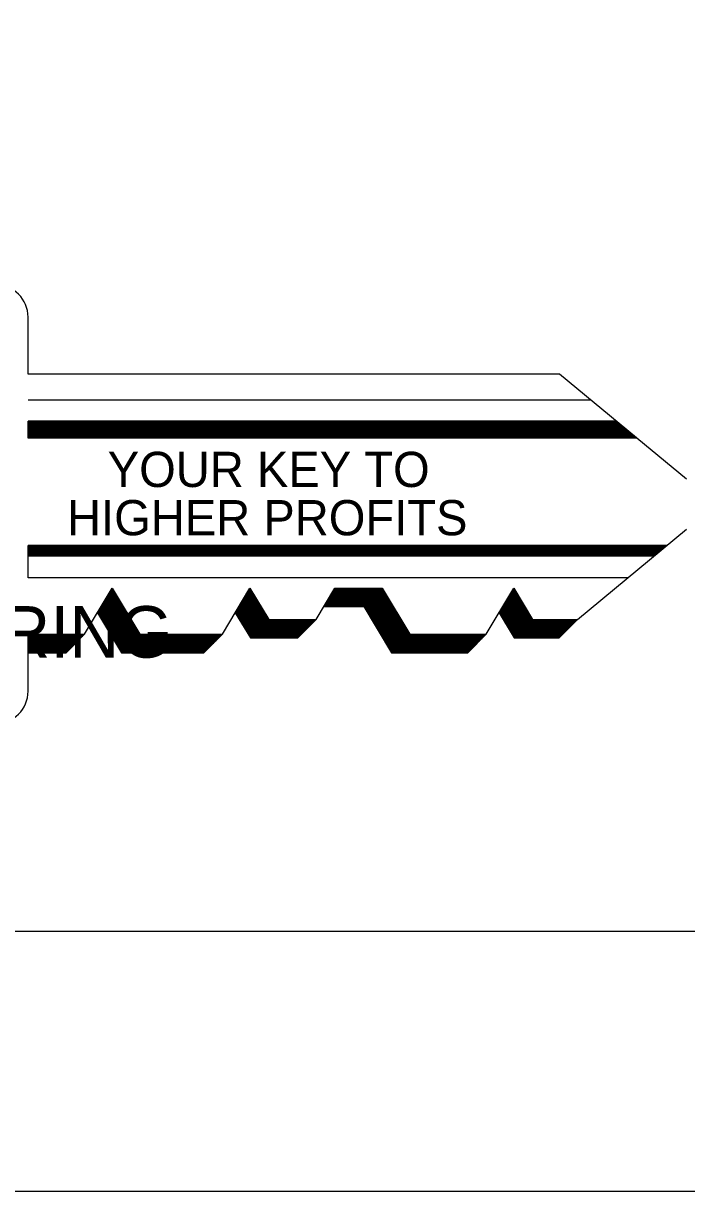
# Model space of a CAD drawing. Extents: x 0 to 53.3, y -2.9 to 37.3.
# Drawn here: x 3.736 to 5.435, y 0.002 to 2.995 of the extents above; entities that cross this region are included whole.
import ezdxf

# ---------------------------------------------------------------- set-up
doc = ezdxf.new("R2010")
doc.units = 0
doc.layers.add('Level 1', color=7, linetype='Continuous')

msp = doc.modelspace()

# ---------------------------------------------------------------- linework, layer by layer
at = {"layer": 'Level 1'}
for p, q in [((3.7484, 2.0961), (3.7484, 2.2419)), ((5.1098, 2.0961), (3.7484, 2.0961)), ((5.3073, 1.9328), (5.1101, 2.0961)), ((5.1904, 2.0294), (3.7484, 2.0294)), ((3.7484, 1.9323), (3.7484, 1.9758)), ((5.2553, 1.9758), (3.7484, 1.9758)), ((5.2566, 1.9748), (3.7484, 1.9748)), ((5.2578, 1.9738), (3.7484, 1.9738)), ((5.2591, 1.9726), (3.7484, 1.9726)), ((5.2606, 1.9714), (3.7484, 1.9714)), ((5.2619, 1.9703), (3.7484, 1.9703)), ((5.2636, 1.9689), (3.7484, 1.9689)), ((5.2649, 1.9678), (3.7484, 1.9678)), ((5.2666, 1.9664), (3.7484, 1.9664)), ((5.2683, 1.9651), (3.7484, 1.9651)), ((5.2696, 1.9639), (3.7484, 1.9639)), ((5.2711, 1.9626), (3.7484, 1.9626)), ((5.2729, 1.9613), (3.7484, 1.9613)), ((5.2743, 1.9601), (3.7484, 1.9601)), ((5.2756, 1.9589), (3.7484, 1.9589)), ((5.2773, 1.9576), (3.7484, 1.9576)), ((5.2789, 1.9563), (3.7484, 1.9563)), ((5.2804, 1.9549), (3.7484, 1.9549)), ((5.2823, 1.9534), (3.7484, 1.9534)), ((5.2838, 1.9523), (3.7484, 1.9523)), ((5.2853, 1.9509), (3.7484, 1.9509)), ((5.2871, 1.9494), (3.7484, 1.9494)), ((5.2888, 1.9481), (3.7484, 1.9481)), ((5.2899, 1.9471), (3.7484, 1.9471)), ((5.2916, 1.9458), (3.7484, 1.9458)), ((5.2708, 1.9629), (5.2703, 1.9634)), ((5.2716, 1.9623), (5.2708, 1.9629)), ((5.2768, 1.9579), (5.2716, 1.9623)), ((5.2791, 1.9561), (5.2768, 1.9579)), ((5.2931, 1.9444), (3.7484, 1.9444)), ((5.2946, 1.9433), (3.7484, 1.9433)), ((5.2959, 1.9421), (3.7484, 1.9421)), ((5.2973, 1.9411), (3.7484, 1.9411)), ((5.2991, 1.9396), (3.7484, 1.9396)), ((5.3003, 1.9386), (3.7484, 1.9386)), ((5.3016, 1.9374), (3.7484, 1.9374)), ((5.3028, 1.9364), (3.7484, 1.9364)), ((5.3041, 1.9354), (3.7484, 1.9354)), ((5.3051, 1.9346), (3.7484, 1.9346)), ((5.3063, 1.9336), (3.7484, 1.9336)), ((5.3071, 1.9329), (3.7484, 1.9329)), ((5.3079, 1.9323), (3.7484, 1.9323)), ((5.3079, 1.9323), (5.3073, 1.9328)), ((5.4354, 1.8269), (5.3079, 1.9323)), ((5.1558, 1.4674), (5.4354, 1.6986)), ((5.3851, 1.6569), (3.7484, 1.6569)), ((3.7484, 1.5743), (3.7484, 1.6569)), ((5.3824, 1.6548), (3.7484, 1.6548)), ((5.3796, 1.6524), (3.7484, 1.6524)), ((5.3764, 1.6498), (3.7484, 1.6498)), ((5.3738, 1.6476), (3.7484, 1.6476)), ((5.3706, 1.6449), (3.7484, 1.6449)), ((5.3678, 1.6426), (3.7484, 1.6426)), ((5.3648, 1.6401), (3.7484, 1.6401)), ((5.3614, 1.6374), (3.7484, 1.6374)), ((5.3584, 1.6349), (3.7484, 1.6349)), ((5.3556, 1.6326), (3.7484, 1.6326)), ((5.3536, 1.6309), (3.7484, 1.6309)), ((5.3518, 1.6294), (3.7484, 1.6294)), ((5.2851, 1.5743), (3.7484, 1.5743)), ((3.8929, 1.4294), (3.9638, 1.5476)), ((3.9518, 1.5273), (3.9759, 1.5273)), ((3.9526, 1.5286), (3.9751, 1.5286)), ((3.9531, 1.5299), (3.9743, 1.5299)), ((3.9539, 1.5313), (3.9736, 1.5313)), ((3.9548, 1.5326), (3.9728, 1.5326)), ((3.9556, 1.5339), (3.9719, 1.5339)), ((3.9564, 1.5353), (3.9711, 1.5353)), ((3.9571, 1.5366), (3.9703, 1.5366)), ((3.9579, 1.5379), (3.9696, 1.5379)), ((3.9588, 1.5393), (3.9688, 1.5393)), ((3.9596, 1.5406), (3.9679, 1.5406)), ((3.9604, 1.5419), (3.9671, 1.5419)), ((3.9611, 1.5433), (3.9664, 1.5433)), ((3.9619, 1.5446), (3.9656, 1.5446)), ((3.9628, 1.5459), (3.9648, 1.5459)), ((3.9638, 1.5476), (4.0344, 1.4294)), ((4.2461, 1.4294), (4.3168, 1.5476)), ((4.3048, 1.5273), (4.3289, 1.5273)), ((4.3056, 1.5286), (4.3281, 1.5286)), ((4.3061, 1.5299), (4.3273, 1.5299)), ((4.3069, 1.5313), (4.3266, 1.5313)), ((4.3078, 1.5326), (4.3258, 1.5326)), ((4.3086, 1.5339), (4.3249, 1.5339)), ((4.3094, 1.5353), (4.3241, 1.5353)), ((4.3101, 1.5366), (4.3233, 1.5366)), ((4.3109, 1.5379), (4.3226, 1.5379)), ((4.3118, 1.5393), (4.3218, 1.5393)), ((4.3126, 1.5406), (4.3209, 1.5406)), ((4.3134, 1.5419), (4.3201, 1.5419)), ((4.3141, 1.5433), (4.3194, 1.5433)), ((4.3148, 1.5443), (4.3188, 1.5443)), ((4.3154, 1.5453), (4.3181, 1.5453)), ((4.3159, 1.5463), (4.3176, 1.5463)), ((4.3168, 1.5476), (4.3649, 1.4674)), ((4.4863, 1.4674), (4.5343, 1.5476)), ((4.5221, 1.5273), (4.6678, 1.5273)), ((4.5229, 1.5286), (4.6669, 1.5286)), ((4.5238, 1.5299), (4.6661, 1.5299)), ((4.5244, 1.5313), (4.6654, 1.5313)), ((4.5253, 1.5326), (4.6646, 1.5326)), ((4.5261, 1.5339), (4.6638, 1.5339)), ((4.5269, 1.5353), (4.6629, 1.5353)), ((4.5276, 1.5366), (4.6621, 1.5366)), ((4.5284, 1.5379), (4.6614, 1.5379)), ((4.5293, 1.5393), (4.6606, 1.5393)), ((4.5301, 1.5406), (4.6598, 1.5406)), ((4.5309, 1.5419), (4.6589, 1.5419)), ((4.5316, 1.5431), (4.6583, 1.5431)), ((4.5323, 1.5443), (4.6576, 1.5443)), ((4.5329, 1.5454), (4.6569, 1.5454)), ((4.5336, 1.5464), (4.6563, 1.5464)), ((4.5343, 1.5476), (4.6556, 1.5476)), ((4.6556, 1.5476), (4.7264, 1.4294)), ((4.9218, 1.4294), (4.9926, 1.5476)), ((4.9806, 1.5273), (5.0048, 1.5273)), ((4.9814, 1.5286), (5.0039, 1.5286)), ((4.9819, 1.5299), (5.0031, 1.5299)), ((4.9828, 1.5313), (5.0024, 1.5313)), ((4.9836, 1.5326), (5.0016, 1.5326)), ((4.9844, 1.5339), (5.0008, 1.5339)), ((4.9853, 1.5353), (4.9999, 1.5353)), ((4.9859, 1.5366), (4.9991, 1.5366)), ((4.9868, 1.5379), (4.9984, 1.5379)), ((4.9876, 1.5393), (4.9976, 1.5393)), ((4.9884, 1.5406), (4.9968, 1.5406)), ((4.9893, 1.5419), (4.9959, 1.5419)), ((4.9899, 1.5433), (4.9953, 1.5433)), ((4.9906, 1.5443), (4.9946, 1.5443)), ((4.9926, 1.5476), (5.0406, 1.4674)), ((3.9341, 1.4979), (3.9934, 1.4979)), ((3.9349, 1.4993), (3.9926, 1.4993)), ((3.9358, 1.5006), (3.9919, 1.5006)), ((3.9366, 1.5019), (3.9911, 1.5019)), ((3.9374, 1.5033), (3.9903, 1.5033)), ((3.9383, 1.5046), (3.9894, 1.5046)), ((3.9391, 1.5059), (3.9888, 1.5059)), ((3.9396, 1.5073), (3.9879, 1.5073)), ((3.9404, 1.5086), (3.9871, 1.5086)), ((3.9413, 1.5099), (3.9863, 1.5099)), ((3.9419, 1.5113), (3.9854, 1.5113)), ((3.9428, 1.5126), (3.9848, 1.5126)), ((3.9436, 1.5139), (3.9839, 1.5139)), ((3.9444, 1.5153), (3.9831, 1.5153)), ((3.9453, 1.5166), (3.9823, 1.5166)), ((3.9459, 1.5179), (3.9814, 1.5179)), ((3.9468, 1.5193), (3.9808, 1.5193)), ((3.9476, 1.5206), (3.9799, 1.5206)), ((3.9484, 1.5219), (3.9791, 1.5219)), ((3.9493, 1.5233), (3.9783, 1.5233)), ((3.9501, 1.5246), (3.9776, 1.5246)), ((3.9509, 1.5259), (3.9768, 1.5259)), ((4.2871, 1.4979), (4.3464, 1.4979)), ((4.2879, 1.4993), (4.3456, 1.4993)), ((4.2888, 1.5006), (4.3449, 1.5006)), ((4.2896, 1.5019), (4.3441, 1.5019)), ((4.2904, 1.5033), (4.3433, 1.5033)), ((4.2913, 1.5046), (4.3424, 1.5046)), ((4.2921, 1.5059), (4.3418, 1.5059)), ((4.2926, 1.5073), (4.3409, 1.5073)), ((4.2934, 1.5086), (4.3401, 1.5086)), ((4.2943, 1.5099), (4.3393, 1.5099)), ((4.2949, 1.5113), (4.3384, 1.5113)), ((4.2958, 1.5126), (4.3378, 1.5126)), ((4.2966, 1.5139), (4.3369, 1.5139)), ((4.2974, 1.5153), (4.3361, 1.5153)), ((4.2983, 1.5166), (4.3353, 1.5166)), ((4.2989, 1.5179), (4.3344, 1.5179)), ((4.2998, 1.5193), (4.3338, 1.5193)), ((4.3006, 1.5206), (4.3329, 1.5206)), ((4.3014, 1.5219), (4.3321, 1.5219)), ((4.3023, 1.5233), (4.3313, 1.5233)), ((4.3031, 1.5246), (4.3306, 1.5246)), ((4.3039, 1.5259), (4.3298, 1.5259)), ((4.5061, 1.5006), (4.6838, 1.5006)), ((4.5061, 1.5004), (4.6084, 1.5004)), ((4.5069, 1.5019), (4.6829, 1.5019)), ((4.5078, 1.5033), (4.6821, 1.5033)), ((4.5086, 1.5046), (4.6813, 1.5046)), ((4.5093, 1.5059), (4.6806, 1.5059)), ((4.5101, 1.5073), (4.6798, 1.5073)), ((4.5109, 1.5086), (4.6789, 1.5086)), ((4.5118, 1.5099), (4.6781, 1.5099)), ((4.5124, 1.5113), (4.6773, 1.5113)), ((4.5133, 1.5126), (4.6766, 1.5126)), ((4.5141, 1.5139), (4.6758, 1.5139)), ((4.5149, 1.5153), (4.6749, 1.5153)), ((4.5158, 1.5166), (4.6741, 1.5166)), ((4.5164, 1.5179), (4.6733, 1.5179)), ((4.5173, 1.5193), (4.6726, 1.5193)), ((4.5181, 1.5206), (4.6718, 1.5206)), ((4.5189, 1.5219), (4.6709, 1.5219)), ((4.5198, 1.5233), (4.6701, 1.5233)), ((4.5204, 1.5246), (4.6694, 1.5246)), ((4.5213, 1.5259), (4.6686, 1.5259)), ((4.6084, 1.5004), (4.6793, 1.3823)), ((4.6091, 1.4993), (4.6844, 1.4993)), ((4.6099, 1.4979), (4.6853, 1.4979)), ((4.9629, 1.4979), (5.0223, 1.4979)), ((4.9638, 1.4993), (5.0214, 1.4993)), ((4.9646, 1.5006), (5.0208, 1.5006)), ((4.9654, 1.5019), (5.0199, 1.5019)), ((4.9663, 1.5033), (5.0191, 1.5033)), ((4.9671, 1.5046), (5.0183, 1.5046)), ((4.9679, 1.5059), (5.0176, 1.5059)), ((4.9684, 1.5073), (5.0168, 1.5073)), ((4.9693, 1.5086), (5.0159, 1.5086)), ((4.9701, 1.5099), (5.0151, 1.5099)), ((4.9708, 1.5113), (5.0143, 1.5113)), ((4.9716, 1.5126), (5.0136, 1.5126)), ((4.9724, 1.5139), (5.0128, 1.5139)), ((4.9733, 1.5153), (5.0119, 1.5153)), ((4.9741, 1.5166), (5.0111, 1.5166)), ((4.9748, 1.5179), (5.0103, 1.5179)), ((4.9756, 1.5193), (5.0096, 1.5193)), ((4.9764, 1.5206), (5.0088, 1.5206)), ((4.9773, 1.5219), (5.0079, 1.5219)), ((4.9781, 1.5233), (5.0071, 1.5233)), ((4.9789, 1.5246), (5.0064, 1.5246)), ((4.9798, 1.5259), (5.0056, 1.5259)), ((3.9261, 1.4846), (3.9873, 1.3823)), ((3.9261, 1.4846), (4.0014, 1.4846)), ((3.9268, 1.4859), (4.0006, 1.4859)), ((3.9269, 1.4833), (4.0023, 1.4833)), ((3.9276, 1.4873), (3.9998, 1.4873)), ((3.9278, 1.4819), (4.0031, 1.4819)), ((3.9284, 1.4886), (3.9991, 1.4886)), ((3.9284, 1.4806), (4.0038, 1.4806)), ((3.9293, 1.4899), (3.9983, 1.4899)), ((3.9293, 1.4793), (4.0046, 1.4793)), ((3.9299, 1.4913), (3.9974, 1.4913)), ((3.9301, 1.4779), (4.0051, 1.4779)), ((3.9308, 1.4926), (3.9966, 1.4926)), ((3.9309, 1.4766), (4.0059, 1.4766)), ((3.9316, 1.4939), (3.9959, 1.4939)), ((3.9316, 1.4753), (4.0068, 1.4753)), ((3.9324, 1.4953), (3.9951, 1.4953)), ((3.9324, 1.4739), (4.0076, 1.4739)), ((3.9333, 1.4966), (3.9943, 1.4966)), ((3.9333, 1.4726), (4.0084, 1.4726)), ((3.9341, 1.4713), (4.0093, 1.4713)), ((3.9349, 1.4699), (4.0101, 1.4699)), ((3.9356, 1.4686), (4.0109, 1.4686)), ((3.9364, 1.4673), (4.0118, 1.4673)), ((4.2791, 1.4846), (4.3178, 1.4203)), ((4.2791, 1.4846), (4.3544, 1.4846)), ((4.2798, 1.4859), (4.3536, 1.4859)), ((4.2799, 1.4833), (4.3553, 1.4833)), ((4.2806, 1.4873), (4.3528, 1.4873)), ((4.2808, 1.4819), (4.3561, 1.4819)), ((4.2814, 1.4886), (4.3521, 1.4886)), ((4.2814, 1.4806), (4.3568, 1.4806)), ((4.2823, 1.4899), (4.3513, 1.4899)), ((4.2823, 1.4793), (4.3576, 1.4793)), ((4.2829, 1.4913), (4.3504, 1.4913)), ((4.2831, 1.4779), (4.3581, 1.4779)), ((4.2838, 1.4926), (4.3496, 1.4926)), ((4.2839, 1.4766), (4.3589, 1.4766)), ((4.2846, 1.4939), (4.3489, 1.4939)), ((4.2846, 1.4753), (4.3598, 1.4753)), ((4.2854, 1.4953), (4.3481, 1.4953)), ((4.2854, 1.4739), (4.3606, 1.4739)), ((4.2863, 1.4966), (4.3473, 1.4966)), ((4.2863, 1.4726), (4.3614, 1.4726)), ((4.2871, 1.4713), (4.3623, 1.4713)), ((4.2879, 1.4699), (4.3631, 1.4699)), ((4.2886, 1.4686), (4.3639, 1.4686)), ((4.2894, 1.4673), (4.3648, 1.4673)), ((4.3649, 1.4674), (4.4863, 1.4674)), ((4.4391, 1.4203), (4.4863, 1.4674)), ((4.6108, 1.4966), (4.6861, 1.4966)), ((4.6116, 1.4953), (4.6869, 1.4953)), ((4.6123, 1.4939), (4.6878, 1.4939)), ((4.6131, 1.4926), (4.6884, 1.4926)), ((4.6139, 1.4913), (4.6893, 1.4913)), ((4.6148, 1.4899), (4.6901, 1.4899)), ((4.6156, 1.4886), (4.6909, 1.4886)), ((4.6163, 1.4873), (4.6916, 1.4873)), ((4.6171, 1.4859), (4.6924, 1.4859)), ((4.6179, 1.4846), (4.6933, 1.4846)), ((4.6188, 1.4833), (4.6941, 1.4833)), ((4.6196, 1.4819), (4.6949, 1.4819)), ((4.6203, 1.4806), (4.6956, 1.4806)), ((4.6211, 1.4793), (4.6964, 1.4793)), ((4.6219, 1.4779), (4.6969, 1.4779)), ((4.6228, 1.4766), (4.6978, 1.4766)), ((4.6234, 1.4753), (4.6986, 1.4753)), ((4.6243, 1.4739), (4.6994, 1.4739)), ((4.6251, 1.4726), (4.7003, 1.4726)), ((4.6259, 1.4713), (4.7011, 1.4713)), ((4.6268, 1.4699), (4.7019, 1.4699)), ((4.6274, 1.4686), (4.7028, 1.4686)), ((4.6283, 1.4673), (4.7036, 1.4673)), ((4.9549, 1.4846), (4.9934, 1.4203)), ((4.9549, 1.4846), (5.0303, 1.4846)), ((4.9556, 1.4859), (5.0294, 1.4859)), ((4.9558, 1.4833), (5.0311, 1.4833)), ((4.9564, 1.4873), (5.0286, 1.4873)), ((4.9566, 1.4819), (5.0319, 1.4819)), ((4.9573, 1.4886), (5.0279, 1.4886)), ((4.9573, 1.4806), (5.0326, 1.4806)), ((4.9581, 1.4899), (5.0271, 1.4899)), ((4.9581, 1.4793), (5.0334, 1.4793)), ((4.9588, 1.4913), (5.0263, 1.4913)), ((4.9589, 1.4779), (5.0339, 1.4779)), ((4.9596, 1.4926), (5.0254, 1.4926)), ((4.9598, 1.4766), (5.0348, 1.4766)), ((4.9604, 1.4939), (5.0248, 1.4939)), ((4.9604, 1.4753), (5.0356, 1.4753)), ((4.9613, 1.4953), (5.0239, 1.4953)), ((4.9613, 1.4739), (5.0364, 1.4739)), ((4.9621, 1.4966), (5.0231, 1.4966)), ((4.9621, 1.4726), (5.0373, 1.4726)), ((4.9629, 1.4713), (5.0381, 1.4713)), ((4.9638, 1.4699), (5.0389, 1.4699)), ((4.9644, 1.4686), (5.0398, 1.4686)), ((4.9653, 1.4673), (5.0406, 1.4673)), ((5.0406, 1.4674), (5.1558, 1.4674)), ((5.1086, 1.4203), (5.1558, 1.4674)), ((3.9373, 1.4659), (4.0126, 1.4659)), ((3.9379, 1.4649), (4.0133, 1.4649)), ((3.9386, 1.4636), (4.0139, 1.4636)), ((3.9394, 1.4623), (4.0148, 1.4623)), ((3.9403, 1.4608), (4.0158, 1.4608)), ((3.9413, 1.4591), (4.0168, 1.4591)), ((3.9423, 1.4576), (4.0176, 1.4576)), ((3.9433, 1.4558), (4.0188, 1.4558)), ((3.9443, 1.4541), (4.0196, 1.4541)), ((3.9456, 1.4521), (4.0209, 1.4521)), ((3.9466, 1.4503), (4.0219, 1.4503)), ((3.9478, 1.4483), (4.0231, 1.4483)), ((3.9489, 1.4463), (4.0244, 1.4463)), ((3.9499, 1.4446), (4.0254, 1.4446)), ((3.9509, 1.4429), (4.0264, 1.4429)), ((3.9523, 1.4409), (4.0276, 1.4409)), ((3.9533, 1.4391), (4.0286, 1.4391)), ((3.9544, 1.4371), (4.0298, 1.4371)), ((4.2903, 1.4659), (4.3656, 1.4659)), ((4.2909, 1.4649), (4.3663, 1.4649)), ((4.2916, 1.4636), (4.3669, 1.4636)), ((4.2924, 1.4623), (4.3678, 1.4623)), ((4.2933, 1.4608), (4.3688, 1.4608)), ((4.2943, 1.4591), (4.3698, 1.4591)), ((4.2953, 1.4576), (4.3706, 1.4576)), ((4.2958, 1.4569), (4.4758, 1.4569)), ((4.2969, 1.4549), (4.4738, 1.4549)), ((4.2981, 1.4529), (4.4718, 1.4529)), ((4.2993, 1.4511), (4.4699, 1.4511)), ((4.3004, 1.4491), (4.4679, 1.4491)), ((4.3016, 1.4471), (4.4659, 1.4471)), ((4.3028, 1.4451), (4.4639, 1.4451)), ((4.3041, 1.4431), (4.4619, 1.4431)), ((4.3048, 1.4418), (4.4606, 1.4418)), ((4.3058, 1.4403), (4.4591, 1.4403)), ((4.3069, 1.4383), (4.4571, 1.4383)), ((4.3418, 1.4658), (4.4846, 1.4658)), ((4.3418, 1.4643), (4.4831, 1.4643)), ((4.3418, 1.4628), (4.4816, 1.4628)), ((4.3418, 1.4609), (4.4798, 1.4609)), ((4.3418, 1.4591), (4.4779, 1.4591)), ((4.6291, 1.4659), (4.7044, 1.4659)), ((4.6298, 1.4649), (4.7051, 1.4649)), ((4.6304, 1.4636), (4.7058, 1.4636)), ((4.6313, 1.4623), (4.7066, 1.4623)), ((4.6321, 1.4608), (4.7076, 1.4608)), ((4.6331, 1.4591), (4.7086, 1.4591)), ((4.6341, 1.4576), (4.7094, 1.4576)), ((4.6351, 1.4558), (4.7106, 1.4558)), ((4.6361, 1.4541), (4.7114, 1.4541)), ((4.6374, 1.4521), (4.7128, 1.4521)), ((4.6384, 1.4503), (4.7138, 1.4503)), ((4.6396, 1.4483), (4.7149, 1.4483)), ((4.6408, 1.4463), (4.7163, 1.4463)), ((4.6418, 1.4446), (4.7173, 1.4446)), ((4.6428, 1.4429), (4.7183, 1.4429)), ((4.6441, 1.4409), (4.7194, 1.4409)), ((4.6451, 1.4391), (4.7204, 1.4391)), ((4.6463, 1.4371), (4.7216, 1.4371)), ((4.9661, 1.4659), (5.0414, 1.4659)), ((4.9668, 1.4649), (5.0421, 1.4649)), ((4.9674, 1.4636), (5.0428, 1.4636)), ((4.9683, 1.4623), (5.0436, 1.4623)), ((4.9691, 1.4608), (5.0446, 1.4608)), ((4.9701, 1.4591), (5.0456, 1.4591)), ((4.9711, 1.4576), (5.0464, 1.4576)), ((4.9716, 1.4569), (5.1453, 1.4569)), ((4.9728, 1.4549), (5.1433, 1.4549)), ((4.9739, 1.4529), (5.1413, 1.4529)), ((4.9751, 1.4511), (5.1394, 1.4511)), ((4.9763, 1.4491), (5.1374, 1.4491)), ((4.9774, 1.4471), (5.1354, 1.4471)), ((4.9786, 1.4451), (5.1334, 1.4451)), ((4.9799, 1.4431), (5.1314, 1.4431)), ((4.9806, 1.4418), (5.1301, 1.4418)), ((4.9816, 1.4403), (5.1286, 1.4403)), ((4.9828, 1.4383), (5.1266, 1.4383)), ((5.0176, 1.4658), (5.1541, 1.4658)), ((5.0176, 1.4643), (5.1526, 1.4643)), ((5.0176, 1.4628), (5.1511, 1.4628)), ((5.0176, 1.4609), (5.1493, 1.4609)), ((5.0176, 1.4591), (5.1474, 1.4591)), ((3.7484, 1.2836), (3.7484, 1.4294)), ((3.7484, 1.4294), (3.8929, 1.4294)), ((3.7484, 1.4278), (3.8913, 1.4278)), ((3.7484, 1.4263), (3.8898, 1.4263)), ((3.7484, 1.4248), (3.8883, 1.4248)), ((3.7484, 1.4229), (3.8864, 1.4229)), ((3.7484, 1.4211), (3.8846, 1.4211)), ((3.7484, 1.4189), (3.8824, 1.4189)), ((3.7484, 1.4169), (3.8804, 1.4169)), ((3.7484, 1.4149), (3.8784, 1.4149)), ((3.7484, 1.4131), (3.8766, 1.4131)), ((3.7484, 1.4111), (3.8746, 1.4111)), ((3.7484, 1.4091), (3.8726, 1.4091)), ((3.7484, 1.4071), (3.8706, 1.4071)), ((3.8458, 1.3823), (3.8929, 1.4294)), ((3.9561, 1.4344), (4.0314, 1.4344)), ((3.9574, 1.4323), (4.0328, 1.4323)), ((3.9588, 1.4299), (4.0341, 1.4299)), ((3.9601, 1.4278), (4.2444, 1.4278)), ((3.9609, 1.4263), (4.2429, 1.4263)), ((3.9619, 1.4248), (4.2414, 1.4248)), ((3.9629, 1.4229), (4.2396, 1.4229)), ((3.9641, 1.4211), (4.2378, 1.4211)), ((3.9654, 1.4189), (4.2356, 1.4189)), ((3.9666, 1.4169), (4.2336, 1.4169)), ((3.9678, 1.4149), (4.2316, 1.4149)), ((3.9688, 1.4131), (4.2298, 1.4131)), ((3.9701, 1.4111), (4.2278, 1.4111)), ((3.9713, 1.4091), (4.2258, 1.4091)), ((3.9724, 1.4071), (4.2238, 1.4071)), ((4.0344, 1.4294), (4.2461, 1.4294)), ((4.1989, 1.3823), (4.2461, 1.4294)), ((4.3081, 1.4363), (4.4551, 1.4363)), ((4.3091, 1.4346), (4.4534, 1.4346)), ((4.3104, 1.4324), (4.4513, 1.4324)), ((4.3116, 1.4304), (4.4493, 1.4304)), ((4.3129, 1.4284), (4.4473, 1.4284)), ((4.3139, 1.4266), (4.4454, 1.4266)), ((4.3154, 1.4243), (4.4431, 1.4243)), ((4.3166, 1.4223), (4.4411, 1.4223)), ((4.3178, 1.4203), (4.4391, 1.4203)), ((4.6479, 1.4344), (4.7233, 1.4344)), ((4.6493, 1.4323), (4.7246, 1.4323)), ((4.6506, 1.4299), (4.7259, 1.4299)), ((4.6519, 1.4278), (4.9201, 1.4278)), ((4.6528, 1.4263), (4.9186, 1.4263)), ((4.6538, 1.4248), (4.9171, 1.4248)), ((4.6548, 1.4229), (4.9153, 1.4229)), ((4.6559, 1.4211), (4.9134, 1.4211)), ((4.6573, 1.4189), (4.9113, 1.4189)), ((4.6584, 1.4169), (4.9093, 1.4169)), ((4.6596, 1.4149), (4.9073, 1.4149)), ((4.6606, 1.4131), (4.9054, 1.4131)), ((4.6619, 1.4111), (4.9034, 1.4111)), ((4.6631, 1.4091), (4.9014, 1.4091)), ((4.6643, 1.4071), (4.8994, 1.4071)), ((4.7264, 1.4294), (4.9218, 1.4294)), ((4.8746, 1.3823), (4.9218, 1.4294)), ((4.9839, 1.4363), (5.1246, 1.4363)), ((4.9849, 1.4346), (5.1229, 1.4346)), ((4.9863, 1.4324), (5.1208, 1.4324)), ((4.9874, 1.4304), (5.1188, 1.4304)), ((4.9888, 1.4284), (5.1168, 1.4284)), ((4.9898, 1.4266), (5.1149, 1.4266)), ((4.9913, 1.4243), (5.1126, 1.4243)), ((4.9924, 1.4223), (5.1106, 1.4223)), ((4.9934, 1.4203), (5.1086, 1.4203)), ((3.7484, 1.4051), (3.8686, 1.4051)), ((3.7484, 1.4038), (3.8673, 1.4038)), ((3.7484, 1.4023), (3.8658, 1.4023)), ((3.7484, 1.4003), (3.8638, 1.4003)), ((3.7484, 1.3983), (3.8618, 1.3983)), ((3.7484, 1.3966), (3.8601, 1.3966)), ((3.7484, 1.3944), (3.8579, 1.3944)), ((3.7484, 1.3924), (3.8559, 1.3924)), ((3.7484, 1.3904), (3.8539, 1.3904)), ((3.7484, 1.3886), (3.8521, 1.3886)), ((3.7484, 1.3863), (3.8498, 1.3863)), ((3.7484, 1.3843), (3.8478, 1.3843)), ((3.7484, 1.3823), (3.8458, 1.3823)), ((3.9736, 1.4051), (4.2218, 1.4051)), ((3.9744, 1.4038), (4.2204, 1.4038)), ((3.9753, 1.4023), (4.2189, 1.4023)), ((3.9764, 1.4003), (4.2169, 1.4003)), ((3.9778, 1.3983), (4.2149, 1.3983)), ((3.9788, 1.3966), (4.2133, 1.3966)), ((3.9799, 1.3944), (4.2111, 1.3944)), ((3.9813, 1.3924), (4.2091, 1.3924)), ((3.9824, 1.3904), (4.2071, 1.3904)), ((3.9834, 1.3886), (4.2053, 1.3886)), ((3.9849, 1.3863), (4.2029, 1.3863)), ((3.9861, 1.3843), (4.2009, 1.3843)), ((3.9873, 1.3823), (4.1989, 1.3823)), ((4.6654, 1.4051), (4.8974, 1.4051)), ((4.6663, 1.4038), (4.8961, 1.4038)), ((4.6671, 1.4023), (4.8946, 1.4023)), ((4.6683, 1.4003), (4.8926, 1.4003)), ((4.6696, 1.3983), (4.8906, 1.3983)), ((4.6706, 1.3966), (4.8889, 1.3966)), ((4.6718, 1.3944), (4.8868, 1.3944)), ((4.6731, 1.3924), (4.8848, 1.3924)), ((4.6743, 1.3904), (4.8828, 1.3904)), ((4.6753, 1.3886), (4.8809, 1.3886)), ((4.6768, 1.3863), (4.8786, 1.3863)), ((4.6779, 1.3843), (4.8766, 1.3843)), ((4.6793, 1.3823), (4.8746, 1.3823))]:
    msp.add_line(p, q, dxfattribs=at)
for points in [[(-0.0026, 37.3348), (53.3308, 37.3348), (53.3308, 0.0015), (-0.0026, 0.0015)], [(1.9974, 36.6682), (52.6641, 36.6682), (52.6641, 0.6682), (1.9974, 0.6682)]]:
    msp.add_lwpolyline(points, close=True, dxfattribs=at)
for centre, start, end in [((3.6651, 2.2419), 0, 90), ((3.6651, 1.2836), 270, 0)]:
    msp.add_arc(centre, 0.0833, start, end, dxfattribs=at)

# ---------------------------------------------------------------- texts
for s, height, p in [('YOUR KEY TO', 0.090249, (3.9524, 1.8068)), ('HIGHER PROFITS', 0.090249, (3.8481, 1.6831)), ('ENGINEERING', 0.13199, (2.8833, 1.3696))]:
    msp.add_text(s, height=height, dxfattribs=at).set_placement(p)

doc.saveas('drawing.dxf')
